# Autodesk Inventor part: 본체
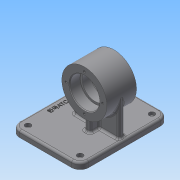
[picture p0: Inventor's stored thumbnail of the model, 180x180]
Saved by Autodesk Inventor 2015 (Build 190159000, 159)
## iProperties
Created: 2019-09
Part Number: 본체
Material: 일반
Document SubType Name: Modeling
Designer: user
Density: 1 g/cm^3
Appearance: 기본값
Author: user
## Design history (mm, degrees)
sketch "스케치1"
  geometry: C1 r 32 at (0, 0); 1 further point
  constraints: 1 centre point, 1 coincident
  dimensions: "d0" = 64 diameter of C1
extrude "돌출1" new body sketch "스케치1" stored distance "d1" = 42; taper "d2" = 0 deg
sketch "스케치2"
  geometry: L1 (32, -21)-(-32, -21) reference; L2 (-32, -21)-(-32, 21) reference; L3 (-32, 21)-(32, 21) reference; L4 (32, 21)-(32, -21) reference; L5 (0, 21)-(0, -21); L6 (21, 21)-(21, 6); L7 (21, 6)-(18, 6); L8 (18, 6)-(18, -6); L9 (18, -6)-(21, -6); L10 (21, -6)-(21, -21); 1 further point
  constraints: 12 end point, 4 point on line, 3 perpendicular, 2 midpoint, 1 vertical
  dimensions: "d3" = 15 distance of L6.start L6.end (= d6); "d4" = 36 diameter of L8 L5; "d5" = 42 diameter of L10 L5; "d6" = 15 distance of L9.end L10.end
revolve "회전1" sketch "스케치2" stored, may be unused: angle "d7" = 90 deg
chamfer "모따기1" distance "d8" = 1; stored, may be unused: second distance "d9" = 2, angle "d10" = 45 deg
fillet "모깎기1" dims "d11" = 0.3
sketch "스케치3"
  geometry: C1 r 32 at (0, 0) reference; 1 further point
  constraints: 1 vertical alignment
  dimensions: "d12" = 26 distance of point (0, 26) C1.centre
hole "구멍1" sketch "스케치3" at (0, 26) diameter "d13" = 3.242; stored, may be unused: countersink angle "d17" = 90 deg, drill point angle "d19" = 118 deg; dims "d14" = 8, "d15" = 4, "d16" = 2, "d18" = 10
node "작업축1"
  node "작업 평면1"
  node "작업 평면2"
sketch "스케치4"
  geometry: L1 (-36, 29.4)-(-36, -29.4) reference; L2 (62, 63)-(-36, 63); L3 (-36, 63)-(-36, -63); L4 (-36, -63)-(62, -63); L5 (62, -63)-(62, 63); L6 (62, 63)-(-36, -63); L7 (-36, 63)-(62, -63); 3 further points
  constraints: 12 end point, 3 midpoint, 2 parallel, 1 horizontal, 1 horizontal alignment, 1 perpendicular, 1 point on line
  dimensions: "d25" = 126 distance of L4.end L2.start; "d26" = 98 distance of L2.start L2.end
extrude "돌출2" join sketch "스케치4" distance "d27" = 9; taper "d28" = 0 deg
fillet "모깎기2" dims "d29" = 12
fillet "모깎기3" dims "d30" = 3
sketch "스케치5"
  geometry: L1 (-50, -51)-(24, -51); L2 (24, -51)-(24, 51); L3 (24, 51)-(-50, 51); L4 (-50, 51)-(-50, -51); A1 r 9 centre (-50, -51) between (-59, -51) and (-50, -60) reference; A2 r 9 centre (24, 51) between (33, 51) and (24, 60) reference; 5 further points
  constraints: 8 end point, 4 coincident, 2 parallel, 1 horizontal, 1 perpendicular
hole "구멍2" sketch "스케치5" at (-50, -51), (24, -51), (24, 51), (-50, 51) diameter "d31" = 4.5; stored, may be unused: countersink angle "d35" = 90 deg, drill point angle "d37" = 0 deg; dims "d32" = 8, "d33" = 8, "d34" = 4.4, "d36" = 10
sketch "스케치6"
  geometry: L1 (4, -17)-(-4, -17); L2 (-4, -17)-(-4, 17); L3 (-4, 17)-(4, 17); L4 (4, 17)-(4, -17); L5 (4, -17)-(-4, 17); L6 (-4, -17)-(4, 17); 1 further point
  constraints: 12 end point, 2 midpoint, 2 parallel, 1 horizontal, 1 perpendicular
  dimensions: "d38" = 8 distance of L2.end L3.end; "d39" = 34 distance of L1.end L2.end
extrude "돌출3" join sketch "스케치6" stored distance "d40" = 9; taper "d41" = 0 deg
sketch "스케치7"
  geometry: L1 (32, -4)-(-32, -4); L2 (-32, -4)-(-32, 4); L3 (-32, 4)-(32, 4); L4 (32, 4)-(32, -4); L5 (32, -4)-(-32, 4); L6 (-32, -4)-(32, 4); 1 further point
  constraints: 12 end point, 2 midpoint, 2 parallel, 1 horizontal, 1 perpendicular
  dimensions: "d42" = 8 distance of L1.end L2.end; "d43" = 32 distance from line of L4 point (0, 0)
extrude "돌출4" join sketch "스케치7" stored distance "d44" = 10; taper "d45" = 0 deg
sketch "스케치8"
  geometry: C1 r 18 at (0, 0) reference; C2 r 18 at (0, 0) reference
extrude "돌출5" cut sketch "스케치8" stored distance "d46" = 20; taper "d47" = 0 deg
fillet "모깎기4" dims "d48" = 3
fillet "모깎기5" dims "d49" = 3
fillet "모깎기6" dims "d50" = 3
node "작업 평면3"
sketch "스케치9"
  geometry: L1 (24, 63)-(-50, 63) reference; L2 (-62, 51)-(-62, -51) reference; 2 further points
  constraints: 1 other
  dimensions: "d52" = 10 distance from line of point (-52, 0) L2; "d53" = 63 distance from line of L1 point (-52, 0)
feature "엠보싱1" sketch "스케치9" dims "d54" = 0.5, "d55" = 0
node "솔리드1"
pattern_circular "원형 패턴1" dims angle "d21" = 360 deg
mirror "대칭1"
node "투영된 루프1"
node "절단 모서리 투영1"
other parameters: "d23" = -59, "d24" = 36
